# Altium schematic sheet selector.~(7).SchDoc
size A4
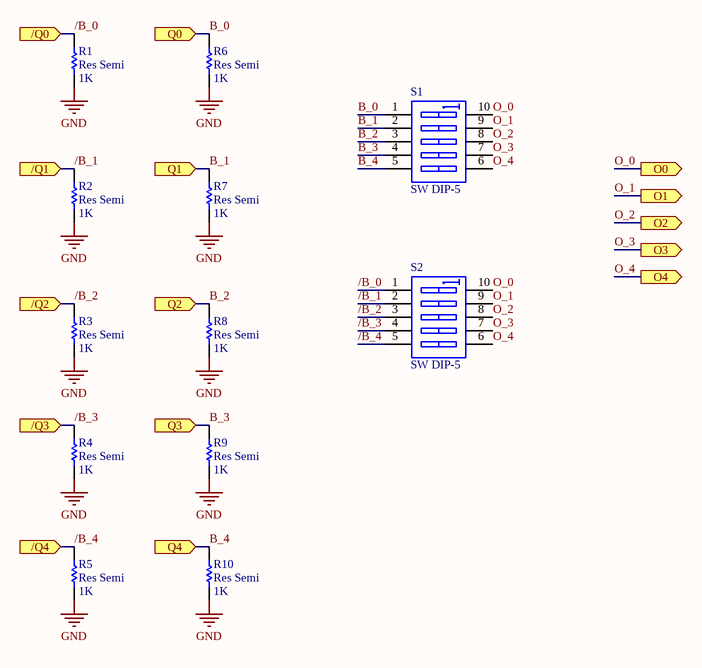
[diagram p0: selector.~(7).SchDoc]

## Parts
R1  Res Semi  value 1K  [2012[0805]]
R2  Res Semi  value 1K  [2012[0805]]
R3  Res Semi  value 1K  [2012[0805]]
R4  Res Semi  value 1K  [2012[0805]]
R5  Res Semi  value 1K  [2012[0805]]
R6  Res Semi  value 1K  [2012[0805]]
R7  Res Semi  value 1K  [2012[0805]]
R8  Res Semi  value 1K  [2012[0805]]
R9  Res Semi  value 1K  [2012[0805]]
R10  Res Semi  value 1K  [2012[0805]]
S1  SW DIP-5  [N10A]
S2  SW DIP-5  [N10A]

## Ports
/Q0 (in), /Q1 (in), /Q2 (in), /Q3 (in), /Q4 (in), O0 (out), O1 (out), O2 (out), O3 (out), O4 (out), Q0 (in), Q1 (in), Q2 (in), Q3 (in), Q4 (in)

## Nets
GND: R1.1 R2.1 R3.1 R4.1 R5.1 R6.1 R7.1 R8.1 R9.1 R10.1
/B_0: R1.2 S2.1(A1) ; port /Q0
/B_1: R2.2 S2.2(A2) ; port /Q1
/B_2: R3.2 S2.3(A3) ; port /Q2
/B_3: R4.2 S2.4(A4) ; port /Q3
/B_4: R5.2 S2.5(A5) ; port /Q4
B_0: R6.2 S1.1(A1) ; port Q0
B_1: R7.2 S1.2(A2) ; port Q1
B_2: R8.2 S1.3(A3) ; port Q2
B_3: R9.2 S1.4(A4) ; port Q3
B_4: R10.2 S1.5(A5) ; port Q4
O_0: S1.10(B1) S2.10(B1) ; port O0
O_1: S1.9(B2) S2.9(B2) ; port O1
O_2: S1.8(B3) S2.8(B3) ; port O2
O_3: S1.7(B4) S2.7(B4) ; port O3
O_4: S1.6(B5) S2.6(B5) ; port O4

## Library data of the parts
R1-R10 = Res Semi: Semiconductor Resistor
S1 S2 = SW DIP-5: DIP Switch, 5 Position, SPST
